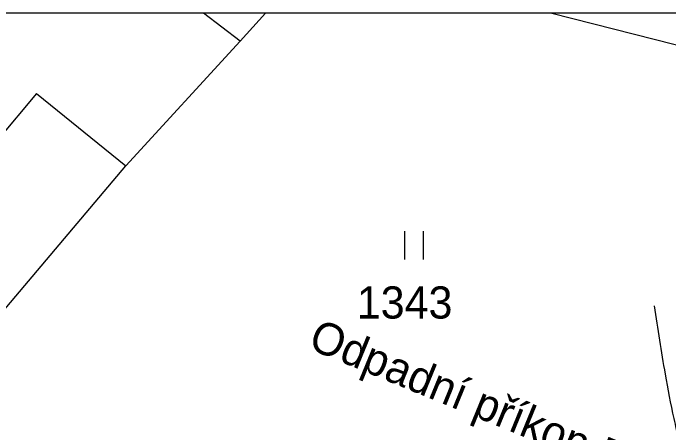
# Model space of a CAD drawing. Extents: x -564037 to -563827, y -1163561 to -1163412.
# Drawn here: x -564012.13 to -563977.47, y -1163434.68 to -1163412.49 of the extents above; entities that cross this region are included whole.
import ezdxf

# ---------------------------------------------------------------- set-up
doc = ezdxf.new("R2010")
doc.units = 0
for name, color, linetype in [('4', 7, 'Continuous'), ('_rám PH2 a PH4', 7, 'Continuous'), ('Hranice parcel', 7, 'Continuous'), ('Parcelní čísla', 7, 'Continuous'), ('Vnitřní kresba', 7, 'Continuous'), ('Vrstva 25', 7, 'Continuous'), ('Značky kultur', 7, 'Continuous')]:
    doc.layers.add(name, color=color, linetype=linetype)

msp = doc.modelspace()

# ---------------------------------------------------------------- linework, layer by layer
at = {"layer": '_rám PH2 a PH4'}
msp.add_line((-563826.505, -1163412.494), (-564036.505, -1163412.494), dxfattribs=at)
at = {"layer": 'Hranice parcel'}
msp.add_line((-564000.13, -1163413.97), (-563998.781, -1163412.494), dxfattribs=at)
for points in [[(-564000.13, -1163413.97), (-564002.064, -1163412.494)], [(-563983.645, -1163412.494), (-563974.99, -1163414.69), (-563964.47, -1163416.08)], [(-564025.34, -1163443.25), (-564021.14, -1163438.29), (-564006.17, -1163420.57), (-564000.13, -1163413.97)]]:
    msp.add_lwpolyline(points, dxfattribs=at)
at = {"layer": 'Vnitřní kresba'}
for q in [(-564025.9, -1163434.51), (-564006.17, -1163420.57)]:
    msp.add_line((-564010.89, -1163416.75), q, dxfattribs=at)
at = {"layer": 'Vrstva 25'}
msp.add_spline([(-563963.083, -1163462.145), (-563963.39, -1163461.716), (-563965.099, -1163459.374), (-563968.902, -1163454.148), (-563969.809, -1163452.732), (-563970.748, -1163451.061), (-563971.513, -1163449.395), (-563972.793, -1163446.36), (-563973.096, -1163445.688), (-563973.41, -1163445.02), (-563973.725, -1163444.353), (-563974.033, -1163443.682), (-563975.446, -1163440.197), (-563976.63, -1163436.253), (-563976.917, -1163435.088), (-563977.191, -1163433.921), (-563977.649, -1163431.571), (-563978.22, -1163427.97)], degree=3, dxfattribs=at)
at = {"layer": 'Značky kultur'}
for p, q in [((-563991.431, -1163425.51), (-563991.431, -1163424.01)), ((-563990.43, -1163425.51), (-563990.43, -1163424.01))]:
    msp.add_line(p, q, dxfattribs=at)

# ---------------------------------------------------------------- texts
at = {"layer": '4'}
msp.add_text('Odpadní příkop PRI1', height=1.70472, rotation=337.7031, dxfattribs=at).set_placement((-563996.602, -1163430.187))
at = {"layer": 'Parcelní čísla'}
msp.add_text('1343', height=1.7, dxfattribs=at).set_placement((-563993.964, -1163428.634))

doc.saveas('drawing.dxf')
